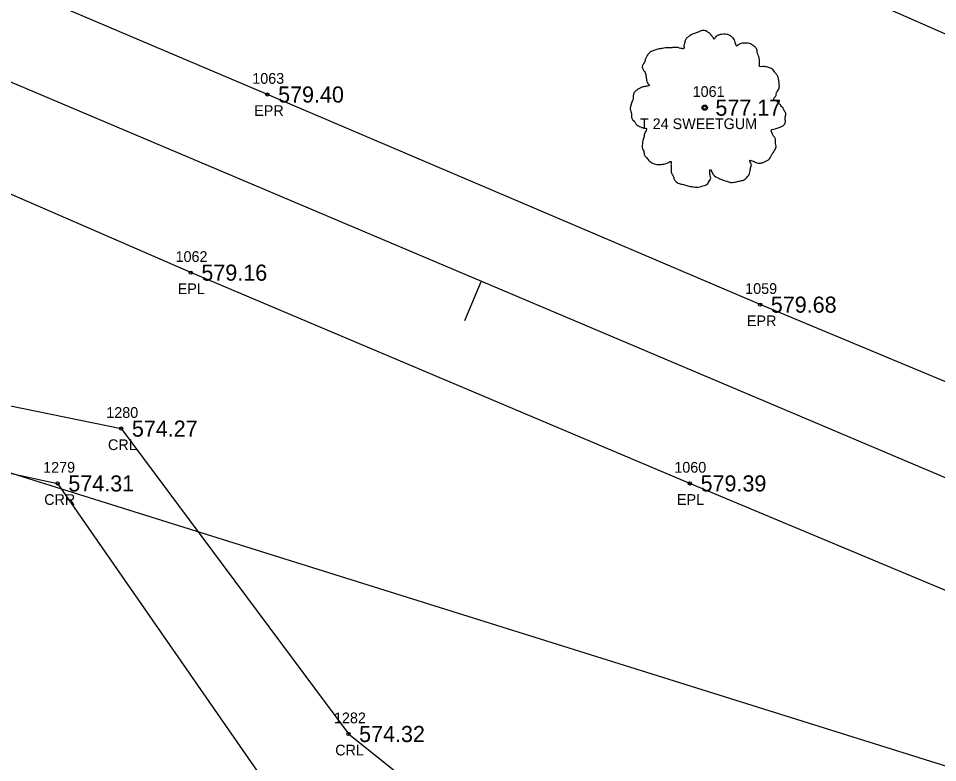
# Model space of a CAD drawing. Extents: x 1664393 to 1667175, y 987029 to 988607.
# Drawn here: x 1665633.2 to 1665718.9, y 987649.2 to 987718.5 of the extents above; entities that cross this region are included whole.
import ezdxf

# ---------------------------------------------------------------- set-up
doc = ezdxf.new("R2010")
doc.units = 0
for name, color, linetype in [('RD_EX_Fence_Other', 7, 'Continuous'), ('RD_EX_H2O', 7, 'Continuous'), ('RD_EX_H2O_txCode', 7, 'Continuous'), ('RD_EX_Road', 7, 'Continuous'), ('RD_EX_Road_txCode', 7, 'Continuous'), ('RD_EX_TX_H2O_ELEV', 7, 'Continuous'), ('RD_EX_TX_Road_ELEV', 7, 'Continuous'), ('RD_EX_TX_VEG_ELEV', 7, 'Continuous'), ('RD_EX_VEG', 7, 'Continuous'), ('RD_EX_VEG_txCode', 7, 'Continuous'), ('RD_HC_Cl', 7, 'Continuous'), ('RD_HC_Data_Tic', 7, 'Continuous'), ('RD_SMD_Locator', 7, 'Continuous')]:
    doc.layers.add(name, color=color, linetype=linetype)

msp = doc.modelspace()

# ---------------------------------------------------------------- linework, layer by layer
at = {"layer": 'RD_EX_Fence_Other'}
msp.add_lwpolyline([(1666177.674, 987530.312), (1666129.013, 987549.765), (1665988.605, 987609.559), (1665898.393, 987649.997), (1665744.328, 987706.222), (1665608.989, 987765.723), (1665620.073, 987798.185), (1665636.547, 987846.221)], dxfattribs=at)
at = {"layer": 'RD_EX_H2O'}
for points in [[(1665565.694, 987792.782), (1665555.482, 987787.59), (1665542.576, 987772.172), (1665532.862, 987767.806), (1665532.862, 987767.806), (1665523.69, 987745.834), (1665522.123, 987740.867), (1665518.202, 987735.792), (1665482.823, 987707.998), (1665483.869, 987700.867), (1665513.494, 987706.089), (1665528.039, 987685.521), (1665561.972, 987665.976), (1665593.475, 987679.218), (1665619.367, 987685.12), (1665642.781, 987680.312), (1665663.972, 987651.849), (1665686.025, 987634.258), (1665705.625, 987627.984), (1665724.83, 987594.973)], [(1665567.265, 987659.004), (1665585.718, 987665.807), (1665597.027, 987673.279), (1665619.208, 987679.023), (1665636.857, 987675.201), (1665656.959, 987646.241), (1665680.504, 987626.228), (1665698.549, 987621.975), (1665717.597, 987587.145)]]:
    msp.add_lwpolyline(points, dxfattribs=at)
at = {"layer": 'RD_EX_Road'}
for points in [[(1666163.185, 987497.623), (1666116.595, 987517.386), (1666070.703, 987536.94), (1666024.42, 987556.434), (1665979.015, 987575.668), (1665932.354, 987595.551), (1665886.935, 987614.539), (1665839.872, 987634.254), (1665794.504, 987653.269), (1665748.805, 987672.511), (1665702.363, 987691.865), (1665656.419, 987711.451), (1665610.33, 987731.033), (1665564.854, 987750.933), (1665531.474, 987764.82)], [(1666156.674, 987480.61), (1666109.284, 987500.741), (1666063.55, 987520.043), (1666017.041, 987539.822), (1665971.114, 987559.142), (1665924.884, 987578.792), (1665879.498, 987597.891), (1665833.217, 987617.382), (1665786.906, 987636.812), (1665741.438, 987656.129), (1665695.815, 987675.204), (1665649.264, 987694.848), (1665603.559, 987714.712), (1665558.4, 987733.869), (1665524.706, 987748.932)]]:
    msp.add_lwpolyline(points, dxfattribs=at)
at = {"layer": 'RD_EX_VEG'}
msp.add_lwpolyline([(1666150.204, 987465.221), (1665963.159, 987547.122), (1665727.121, 987646.514), (1665543.179, 987704.13), (1665449.914, 987737.525), (1665163.848, 987870.347), (1665156.075, 987854.029)], dxfattribs=at)
for centre, radius in [((1665697.2, 987710.228), 0.25), ((1665697.187, 987710.209), 0.0001)]:
    msp.add_circle(centre, radius, dxfattribs=at)
for points in [[(1665697.332, 987717.395), (1665697.032, 987717.42), (1665696.707, 987717.32), (1665696.457, 987717.22), (1665696.232, 987717.145), (1665696.008, 987717.045), (1665695.708, 987716.87), (1665695.483, 987716.67), (1665695.358, 987716.42), (1665695.308, 987716.195), (1665695.258, 987715.92), (1665695.258, 987715.745), (1665695.133, 987715.72), (1665694.983, 987715.745), (1665694.733, 987715.82), (1665694.483, 987715.82), (1665694.233, 987715.82), (1665693.883, 987715.795), (1665693.534, 987715.795), (1665693.259, 987715.745), (1665692.934, 987715.696), (1665692.559, 987715.571), (1665692.209, 987715.446), (1665691.909, 987715.196), (1665691.659, 987714.721), (1665691.534, 987714.371), (1665691.385, 987714.121), (1665691.534, 987713.671), (1665691.709, 987713.322), (1665691.734, 987713.122), (1665691.809, 987712.697), (1665691.909, 987712.472), (1665692.034, 987712.272), (1665691.959, 987712.247), (1665691.584, 987712.197), (1665691.285, 987712.097), (1665690.86, 987711.872), (1665690.635, 987711.647), (1665690.535, 987711.322), (1665690.51, 987710.973), (1665690.41, 987710.773), (1665690.335, 987710.498), (1665690.31, 987710.423), (1665690.26, 987710.098), (1665690.36, 987709.648), (1665690.385, 987709.298), (1665690.51, 987709.073), (1665690.66, 987708.899), (1665690.835, 987708.649), (1665691.235, 987708.424), (1665691.559, 987708.324), (1665691.759, 987708.299), (1665691.584, 987707.799), (1665691.534, 987707.449), (1665691.41, 987707.049), (1665691.41, 987706.974), (1665691.36, 987706.5), (1665691.509, 987706.175), (1665691.584, 987705.8), (1665691.759, 987705.575), (1665692.034, 987705.275), (1665692.359, 987705.05), (1665692.859, 987704.925), (1665693.259, 987704.95), (1665693.834, 987705.125), (1665694.083, 987705.2), (1665694.058, 987705.025), (1665694.083, 987704.65), (1665694.083, 987704.226), (1665694.233, 987703.901), (1665694.333, 987703.626), (1665694.483, 987703.376), (1665694.808, 987703.151), (1665695.208, 987703.076), (1665695.633, 987702.926), (1665696.083, 987702.851), (1665696.582, 987702.826), (1665697.182, 987702.976), (1665697.457, 987703.101), (1665697.557, 987703.276), (1665697.757, 987703.651), (1665697.707, 987703.876), (1665697.732, 987704.475), (1665697.832, 987704.3), (1665698.007, 987703.951), (1665698.506, 987703.651), (1665698.906, 987703.476), (1665699.381, 987703.326), (1665699.681, 987703.251), (1665700.156, 987703.326), (1665700.531, 987703.401), (1665700.905, 987703.526), (1665701.205, 987703.801), (1665701.38, 987704.076), (1665701.43, 987704.35), (1665701.505, 987704.725), (1665701.555, 987704.9)], [(1665701.555, 987704.9), (1665701.48, 987705.075), (1665701.43, 987705.325), (1665701.505, 987705.3), (1665701.68, 987705.25), (1665701.955, 987705.125), (1665702.18, 987705.05), (1665702.505, 987705.075), (1665702.78, 987705.175), (1665703.229, 987705.45), (1665703.504, 987705.925), (1665703.779, 987706.325), (1665703.854, 987706.649), (1665703.804, 987706.874), (1665703.779, 987707.374), (1665703.579, 987707.624), (1665703.529, 987707.749), (1665703.429, 987708.149), (1665703.504, 987708.199), (1665703.779, 987708.249), (1665704.154, 987708.374), (1665704.429, 987708.499), (1665704.654, 987708.674), (1665704.729, 987708.899), (1665704.704, 987709.298), (1665704.754, 987709.698), (1665704.679, 987709.848), (1665704.579, 987709.998), (1665704.504, 987710.198), (1665704.354, 987710.348), (1665704.254, 987710.498), (1665704.154, 987710.598), (1665704.029, 987710.748), (1665703.854, 987710.873), (1665703.704, 987710.923), (1665703.654, 987711.073), (1665703.804, 987711.272), (1665703.854, 987711.372), (1665703.879, 987711.597), (1665704.104, 987711.947), (1665704.154, 987712.347), (1665704.104, 987712.772), (1665704.054, 987713.047), (1665703.904, 987713.322), (1665703.704, 987713.571), (1665703.579, 987713.746), (1665703.404, 987713.871), (1665703.079, 987713.996), (1665702.83, 987714.046), (1665702.48, 987714.046), (1665702.28, 987714.096), (1665702.305, 987714.146), (1665702.305, 987714.296), (1665702.305, 987714.571), (1665702.23, 987715.021), (1665702.08, 987715.521), (1665702.08, 987715.546), (1665701.98, 987715.795), (1665701.755, 987715.995), (1665701.58, 987716.095), (1665701.38, 987716.22), (1665701.13, 987716.245), (1665700.83, 987716.245), (1665700.556, 987716.195), (1665700.356, 987716.095), (1665700.181, 987715.97), (1665700.106, 987716.12), (1665700.006, 987716.42), (1665699.956, 987716.57), (1665699.806, 987716.745), (1665699.581, 987716.945), (1665699.131, 987717.07), (1665698.506, 987716.995), (1665698.207, 987716.795), (1665698.057, 987716.62), (1665698.007, 987716.745), (1665697.807, 987716.945), (1665697.707, 987717.12), (1665697.532, 987717.245), (1665697.382, 987717.345), (1665697.282, 987717.395)]]:
    msp.add_spline(points, degree=3, dxfattribs=at)
at = {"layer": 'RD_HC_Cl'}
msp.add_line((1666160.052, 987489.414), (1664963.07, 987995.795), dxfattribs=at)
at = {"layer": 'RD_HC_Data_Tic'}
msp.add_line((1665676.346, 987694.045), (1665674.787, 987690.361), dxfattribs=at)
at = {"layer": 'RD_SMD_Locator'}
for centre in [(1665656.419, 987711.451), (1665697.2, 987710.228), (1665649.264, 987694.848), (1665702.363, 987691.865), (1665642.781, 987680.312), (1665636.857, 987675.201), (1665695.815, 987675.204), (1665663.972, 987651.849)]:
    msp.add_circle(centre, 0.15, dxfattribs=at)

# ---------------------------------------------------------------- texts
at = {"layer": 'RD_EX_H2O_txCode'}
for s, p in [('1280', (1665641.395, 987681.312)), ('CRL', (1665641.552, 987678.312)), ('1279', (1665635.51, 987676.201)), ('CRR', (1665635.605, 987673.201)), ('1282', (1665662.626, 987652.849)), ('CRL', (1665662.744, 987649.849))]:
    msp.add_text(s, height=1, dxfattribs=at).set_placement(p)
at = {"layer": 'RD_EX_Road_txCode'}
for s, p in [('1063', (1665655.009, 987712.451)), ('EPR', (1665655.19, 987709.451)), ('1062', (1665647.855, 987695.848)), ('EPL', (1665648.059, 987692.848)), ('1059', (1665700.977, 987692.865)), ('EPR', (1665701.135, 987689.865)), ('1060', (1665694.366, 987676.204)), ('EPL', (1665694.61, 987673.204))]:
    msp.add_text(s, height=1, dxfattribs=at).set_placement(p)
at = {"layer": 'RD_EX_TX_H2O_ELEV'}
for s, p in [('574.27', (1665643.781, 987679.562)), ('574.31', (1665637.857, 987674.451)), ('574.32', (1665664.972, 987651.099))]:
    msp.add_text(s, height=1.5, dxfattribs=at).set_placement(p)
at = {"layer": 'RD_EX_TX_Road_ELEV'}
for s, p in [('579.40', (1665657.419, 987710.701)), ('579.16', (1665650.264, 987694.098)), ('579.68', (1665703.363, 987691.115)), ('579.39', (1665696.815, 987674.454))]:
    msp.add_text(s, height=1.5, dxfattribs=at).set_placement(p)
at = {"layer": 'RD_EX_TX_VEG_ELEV'}
msp.add_text('577.17', height=1.5, dxfattribs=at).set_placement((1665698.2, 987709.478))
at = {"layer": 'RD_EX_VEG_txCode'}
for s, p in [('1061', (1665696.074, 987711.228)), ('T 24 SWEETGUM', (1665691.161, 987708.228))]:
    msp.add_text(s, height=1, dxfattribs=at).set_placement(p)

doc.saveas('drawing.dxf')
